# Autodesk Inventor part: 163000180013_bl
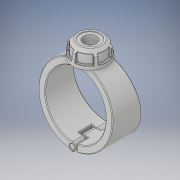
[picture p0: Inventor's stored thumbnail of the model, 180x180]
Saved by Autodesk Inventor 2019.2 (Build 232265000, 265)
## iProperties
Created: 2022-02
Part Number: 163000180013_bl
Material: Generic
Description: Plassadle Threaded 180x1 1/4''
Document SubType Name: Modeling
Designer: comp2
Density: 1 g/cm^3
Appearance: Default
Author: comp2
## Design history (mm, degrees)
derived "16300.ipt"
feature "Solid1::16300.ipt" dims "ScaleForDerivedMember" = 10
feature "Solid2::16300.ipt" dims "ScaleForDerivedMember" = 10
feature "Solid3::16300.ipt" dims "ScaleForDerivedMember" = 10
feature "Solid4::16300.ipt" dims "ScaleForDerivedMember" = 10
tag "TaggingFeature1"
body "Solid1"
body "Solid2"
body "Solid3"
body "Solid4"
other parameters: "d7" = 209 [user parameter], "d8" = 85 deg [user parameter], "d9" = 45 deg [user parameter], "d10" = 102 [user parameter], "d11" = 49 [user parameter], "d12" = 31.57 [user parameter], "d13" = 42.84 [user parameter], "d14" = 58.428 [user parameter], "d42" = 4 [user parameter], "d49" = 4.4 [user parameter], "d51" = 0 [user parameter], "d52" = 28 [user parameter], "d53" = 121 [user parameter], "d54" = 38.5 [user parameter], "d55" = 0 [user parameter], "d56" = 22 [user parameter], "d57" = 22 [user parameter], "d59" = 0 [user parameter], "d61" = 0 [user parameter], "d62" = 38.5 [user parameter], "d63" = 0 [user parameter], "d65" = 0 [user parameter], "d67" = 0 [user parameter], "d69" = 0 [user parameter], "d70" = 1 [user parameter], "d71" = 105.6 [user parameter], "d72" = 0 [user parameter], "d73" = 2 [user parameter], "d78" = 86.7 [user parameter], "d79" = 5.1 [user parameter], "d80" = 60 deg [user parameter], "d81" = 5.1 [user parameter], "d84" = 0 [user parameter], "d85" = 1 [user parameter], "d87" = 360 deg [user parameter], "d122" = 58 [user parameter], "d124" = 42.80128 [user parameter], "d125" = 2.255 [user parameter], "d127" = 264 [user parameter], "d129" = 38.952 [user parameter], "d130" = 33.1092 [user parameter], "d131" = 37.7 [user parameter], "d132" = 45 deg [user parameter], "d133" = 26.39 [user parameter], "d134" = 19.476 [user parameter], "d136" = 0 [user parameter], "d138" = 0 [user parameter], "d1" = 25 [user parameter], "E_" = 54 [user parameter], "E1" = 102 [user parameter], "H1" = 264 [user parameter], "H2" = 58 [user parameter], "H3" = 78 [user parameter], "H_costum" = 49 [user parameter], "Rp" = 38.952 [user parameter], "d128" = 45.1 [user parameter]
